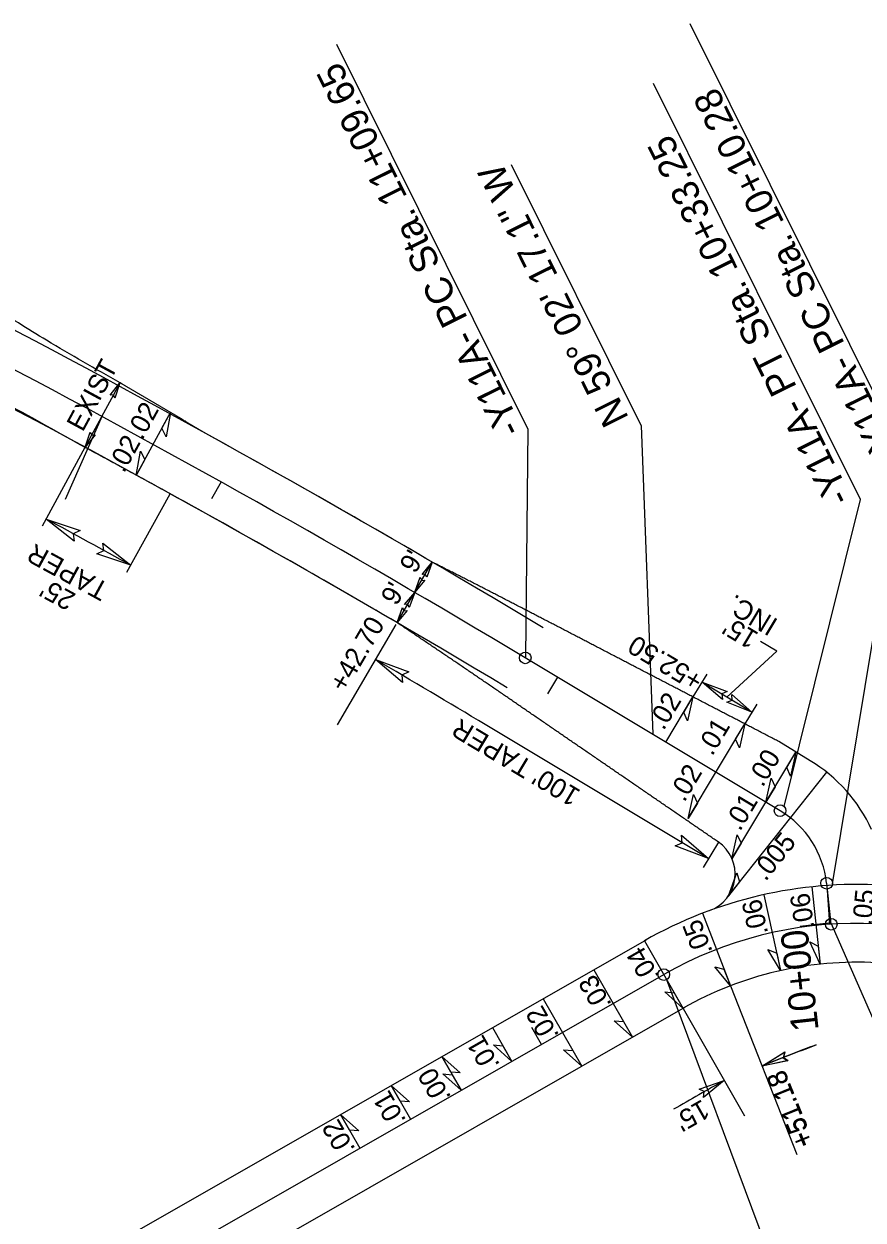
# Model space of a CAD drawing. Extents: x 472216 to 481979, y 489069 to 507339.
# Drawn here: x 475868.8 to 476084.6, y 502331.6 to 502639.2 of the extents above; entities that cross this region are included whole.
import ezdxf

# ---------------------------------------------------------------- set-up
doc = ezdxf.new("R2010")
doc.units = 0
for name, color, linetype in [('Old_Level_12', 7, 'Continuous'), ('Prop Drainage Structure Drop Inlet Grate 2 Narrow Slots and Sag Grates 840 24 CELL', 7, 'Continuous'), ('Prop Drainage Structure Drop Inlet Grate 2 Wide Slots and Sag Grates 840 22 Label', 7, 'Continuous'), ('Prop Drainage Structure Outlet Berm Ditch 850 10 CELL', 7, 'Continuous'), ('Prop Drainage Structure Pipe CSP 15in', 7, 'Continuous'), ('Prop Drainage Structure Pipe RCP 24in Class III Label', 7, 'Continuous'), ('Sheet Block Revision CELL', 7, 'Continuous'), ('Sheet Clip Boundary CELL', 7, 'Continuous'), ('Sheet North Arrow Point CELL', 7, 'Continuous'), ('Sheet PE Seal Cell', 7, 'Continuous'), ('Sheet Plan And Profile CELL', 7, 'Continuous'), ('Sheet Plot Border Outside CELL', 7, 'Continuous'), ('Sheet Profile Grid Major CELL', 7, 'Continuous'), ('Sheet Profile Grid Minor CELL', 7, 'Continuous')]:
    doc.layers.add(name, color=color, linetype=linetype)

msp = doc.modelspace()

# ---------------------------------------------------------------- linework, layer by layer
at = {"layer": 'Old_Level_12'}
for p, q in [((476095.02, 502528.88), (476040.15, 502639.21)), ((475998.49, 502534.91), (475949.28, 502633.88)), ((476083.89, 502516.94), (476030.7, 502623.9)), ((476027.52, 502535.97), (475994.2, 502602.98)), ((475888.94, 502538.42), (475879.42, 502516.88)), ((475997.83, 502476.34), (475998.49, 502534.91)), ((476027.52, 502535.97), (476030.49, 502456.52)), ((476076.71, 502418.03), (476095.02, 502528.88)), ((476064.3, 502437.93), (476083.89, 502516.94)), ((476123.29, 502300.73), (476076.37, 502407.98)), ((476034.08, 502393.42), (476074.2, 502285.86))]:
    msp.add_line(p, q, dxfattribs=at)
for centre in [(475997.73, 502476.18), (476063.24, 502436.87), (476075.23, 502418.22), (476076.4, 502407.68), (476076.4, 502407.68), (476033.34, 502394.73), (476033.34, 502394.73), (476033.34, 502394.73)]:
    msp.add_circle(centre, 1.5, dxfattribs=at)
at = {"layer": 'Prop Drainage Structure Drop Inlet Grate 2 Narrow Slots and Sag Grates 840 24 CELL'}
for points in [[(475906.5, 502539.27), (475905.38, 502533.05), (475904.28, 502535.21)], [(475897.67, 502523.09), (475898.78, 502529.31), (475899.88, 502527.15)], [(476040.85, 502466.13), (476039.48, 502459.95), (476038.47, 502462.16)], [(476054.19, 502459.19), (476052.81, 502453.02), (476051.81, 502455.23)], [(476067.33, 502451.95), (476065.96, 502445.78), (476064.95, 502447.98)], [(476059.6, 502439.06), (476060.97, 502445.23), (476061.98, 502443.02)], [(476039.59, 502434.87), (476040.96, 502441.04), (476041.97, 502438.83)], [(476050.88, 502424.53), (476052.25, 502430.7), (476053.26, 502428.49)], [(476049.96, 502414.95), (476052.12, 502420.9), (476052.83, 502418.58)], [(476073.53, 502397.4), (476070.91, 502403.16), (476073.05, 502402)], [(476063.38, 502395.74), (476060.13, 502401.17), (476062.38, 502400.26)], [(476050.47, 502391.84), (476046.45, 502396.71), (476048.81, 502396.15)], [(476038.29, 502386.04), (476033.58, 502390.26), (476036, 502390.06)], [(476025.27, 502378.6), (476020.56, 502382.82), (476022.98, 502382.62)], [(475994.26, 502372.4), (475989.55, 502376.62), (475991.97, 502376.42)], [(476012.25, 502371.16), (476007.53, 502375.38), (476009.95, 502375.17)], [(475976.28, 502373.64), (475980.99, 502369.43), (475978.57, 502369.63)], [(475981.24, 502364.96), (475976.52, 502369.18), (475978.94, 502368.98)], [(475963.25, 502366.2), (475967.96, 502361.99), (475965.55, 502362.19)], [(475950.23, 502358.76), (475954.94, 502354.54), (475952.52, 502354.75)]]:
    msp.add_lwpolyline(points, close=True, dxfattribs=at)
at = {"layer": 'Prop Drainage Structure Drop Inlet Grate 2 Wide Slots and Sag Grates 840 22 Label'}
for p, q in [((475897.67, 502523.09), (475906.5, 502539.27)), ((476062.4, 502477.9), (476058.21, 502480.41)), ((476049.56, 502466.07), (476062.4, 502477.9)), ((476044.38, 502472.01), (476040.85, 502466.13)), ((476056, 502462.21), (476043.13, 502469.93)), ((476033.87, 502454.49), (476040.85, 502466.13)), ((476057.25, 502464.29), (476054.19, 502459.19)), ((476039.59, 502434.87), (476054.19, 502459.19)), ((476050.88, 502424.53), (476067.33, 502451.95)), ((476049.82, 502414.73), (476075.23, 502446.78)), ((476059.04, 502415.27), (476063.38, 502395.74)), ((476071.44, 502417.29), (476073.53, 502397.4)), ((476043.26, 502410.49), (476050.47, 502391.84)), ((476028.37, 502403.41), (476038.29, 502386.04)), ((476015.35, 502395.97), (476025.27, 502378.6)), ((476050.47, 502391.84), (476067.53, 502348.46)), ((476002.33, 502388.52), (476012.25, 502371.16)), ((476038.29, 502386.04), (476054.11, 502358.36)), ((475989.3, 502381.08), (475994.26, 502372.4)), ((475976.28, 502373.64), (475981.24, 502364.96)), ((475963.25, 502366.2), (475968.21, 502357.52)), ((475950.23, 502358.76), (475955.19, 502350.08))]:
    msp.add_line(p, q, dxfattribs=at)
for points in [[(476048.41, 502465.48), (476043.17, 502469.89), (476049.64, 502467.5), (476048.29, 502466.9)], [(476050.86, 502466.74), (476056, 502462.21), (476049.59, 502464.75), (476050.95, 502465.32)], [(476065.23, 502372.58), (476058.53, 502371.15), (476064.39, 502374.79), (476064.03, 502373.35)], [(476065.34, 502372.66), (476058.65, 502371.2), (476064.48, 502374.86), (476064.14, 502373.43)], [(476042.42, 502365.24), (476048.89, 502367.49), (476043.54, 502363.15), (476043.71, 502364.62)]]:
    msp.add_lwpolyline(points, close=True, dxfattribs=at)
for centre, start, end in [((476392.64, 501524.75), 110.59975, 111.54419), ((476397.41, 501526.65), 110.91536, 111.85981), ((476492.74, 501573.08), 119.19234, 120.13679)]:
    msp.add_arc(centre, 910, start, end, dxfattribs=at)
at = {"layer": 'Prop Drainage Structure Outlet Berm Ditch 850 10 CELL'}
for points in [[(475890.96, 502543.7), (475893.5, 502546.93), (475892.2, 502543), (475891.81, 502543.8)], [(475887.1, 502533.57), (475884.56, 502530.34), (475885.86, 502534.26), (475886.25, 502533.47)], [(475881.74, 502506.22), (475874.57, 502511.87), (475883.29, 502508.96), (475881.51, 502508.1)], [(475889.11, 502505.67), (475896.27, 502500), (475887.56, 502502.93), (475889.33, 502503.78)], [(475971.18, 502497.64), (475973.82, 502500.79), (475972.39, 502496.91), (475972.03, 502497.72)], [(475971.94, 502496.18), (475969.3, 502493.03), (475970.73, 502496.91), (475971.09, 502496.1)], [(475966.64, 502489.87), (475969.29, 502493.02), (475967.86, 502489.14), (475967.49, 502489.95)], [(475967.39, 502488.39), (475964.75, 502485.24), (475966.18, 502489.12), (475966.54, 502488.31)], [(475966.18, 502469.86), (475959.2, 502475.75), (475967.82, 502472.56), (475966.02, 502471.76)], [(476037.93, 502430.54), (476044.85, 502424.59), (476036.26, 502427.87), (476038.07, 502428.65)]]:
    msp.add_lwpolyline(points, close=True, dxfattribs=at)
at = {"layer": 'Prop Drainage Structure Pipe RCP 24in Class III Label'}
for p, q in [((476070.96, 502449.73), (476062.9, 502454.66)), ((475884.66, 502321.3), (476028.98, 502403.75)), ((475894.58, 502303.94), (476038.9, 502386.39))]:
    msp.add_line(p, q, dxfattribs=at)
for centre, radius, start, end in [((474546.93, 500058), 2829, 59.70962, 61.077), ((474546.93, 500058), 2811, 59.70962, 61.077), ((476050.38, 502415.43), 40, 24.464, 59.0381), ((476041.69, 502420.58), 10, 290.1061, 55.6024), ((476082.94, 502307.9), 110, 86.4598, 119.7387), ((476082.94, 502307.9), 90, 86.612, 119.7387)]:
    msp.add_arc(centre, radius, start, end, dxfattribs=at)
for points in [[(475893.53, 502546.91), (475874.64, 502557.84), (475867.39, 502562.3), (475860.29, 502566.99), (475853.18, 502571.68), (475845.92, 502576.15), (475839.15, 502579.89), (475832.27, 502583.43), (475818.29, 502590.07), (475810.52, 502593.49), (475802.68, 502596.74), (475794.84, 502599.98), (475792.99, 502600.76)], [(475884.54, 502530.3), (475864.92, 502541.16), (475834.72, 502557.15), (475828.24, 502560.66), (475821.77, 502564.21), (475808.73, 502571.08), (475797.11, 502576.65)], [(475915.13, 502534.14), (475914.84, 502534.31), (475914.55, 502534.49), (475914.26, 502534.66), (475913.97, 502534.83), (475913.67, 502535.01), (475913.38, 502535.18), (475913.09, 502535.36), (475912.8, 502535.53), (475912.51, 502535.7), (475912.22, 502535.88), (475911.93, 502536.05), (475911.63, 502536.22), (475911.34, 502536.4), (475911.05, 502536.57), (475910.76, 502536.74), (475910.47, 502536.92), (475910.18, 502537.09), (475909.89, 502537.26), (475909.59, 502537.44), (475909.3, 502537.61), (475909.01, 502537.78), (475908.72, 502537.96), (475908.43, 502538.13), (475908.14, 502538.3), (475907.84, 502538.47), (475907.55, 502538.65), (475907.26, 502538.82), (475906.97, 502538.99), (475906.68, 502539.17), (475906.39, 502539.34), (475906.09, 502539.51), (475905.8, 502539.69), (475905.51, 502539.86), (475905.22, 502540.03), (475904.93, 502540.2), (475904.63, 502540.38), (475904.34, 502540.55), (475904.05, 502540.72), (475903.76, 502540.89), (475903.47, 502541.07), (475903.17, 502541.24), (475902.88, 502541.41), (475902.59, 502541.58), (475902.3, 502541.76), (475902.01, 502541.93), (475901.71, 502542.1), (475901.42, 502542.27), (475901.13, 502542.44), (475900.84, 502542.62), (475900.55, 502542.79), (475900.25, 502542.96), (475899.96, 502543.13), (475899.67, 502543.31), (475899.38, 502543.48), (475899.08, 502543.65), (475898.79, 502543.82), (475898.5, 502543.99), (475898.21, 502544.17), (475897.91, 502544.34), (475897.62, 502544.51), (475897.33, 502544.68), (475897.04, 502544.85), (475896.74, 502545.02), (475896.45, 502545.2), (475896.16, 502545.37), (475895.87, 502545.54), (475895.57, 502545.71), (475895.28, 502545.88), (475894.99, 502546.05), (475894.7, 502546.22), (475894.4, 502546.4), (475894.11, 502546.57), (475893.53, 502546.91)], [(475906.42, 502518.38), (475906.13, 502518.55), (475905.83, 502518.71), (475905.54, 502518.87), (475905.24, 502519.03), (475904.95, 502519.2), (475904.65, 502519.36), (475904.36, 502519.52), (475904.06, 502519.68), (475903.77, 502519.84), (475903.47, 502520.01), (475903.18, 502520.17), (475902.88, 502520.33), (475902.59, 502520.49), (475902.29, 502520.65), (475902, 502520.81), (475901.7, 502520.98), (475901.41, 502521.14), (475901.11, 502521.3), (475900.81, 502521.46), (475900.52, 502521.62), (475900.22, 502521.78), (475899.93, 502521.95), (475899.63, 502522.11), (475899.34, 502522.27), (475899.04, 502522.43), (475898.75, 502522.59), (475898.45, 502522.75), (475898.16, 502522.91), (475897.86, 502523.08), (475897.56, 502523.24), (475897.27, 502523.4), (475896.97, 502523.56), (475896.68, 502523.72), (475896.38, 502523.88), (475896.09, 502524.04), (475895.79, 502524.2), (475895.49, 502524.36), (475895.2, 502524.53), (475894.9, 502524.69), (475894.61, 502524.85), (475894.31, 502525.01), (475894.01, 502525.17), (475893.72, 502525.33), (475893.42, 502525.49), (475893.13, 502525.65), (475892.83, 502525.81), (475892.53, 502525.97), (475892.24, 502526.13), (475891.94, 502526.29), (475891.65, 502526.45), (475891.35, 502526.62), (475891.05, 502526.78), (475890.76, 502526.94), (475890.46, 502527.1), (475890.17, 502527.26), (475889.87, 502527.42), (475889.57, 502527.58), (475889.28, 502527.74), (475888.98, 502527.9), (475888.69, 502528.06), (475888.39, 502528.22), (475888.09, 502528.38), (475887.8, 502528.54), (475887.5, 502528.7), (475887.2, 502528.86), (475886.91, 502529.02), (475886.61, 502529.18), (475886.32, 502529.34), (475886.02, 502529.5), (475885.72, 502529.66), (475885.43, 502529.82), (475885.13, 502529.98), (475884.54, 502530.3)], [(476018.46, 502477.78), (476017.86, 502478.09), (476017.26, 502478.4), (476016.66, 502478.72), (476016.06, 502479.03), (476015.45, 502479.34), (476014.85, 502479.65), (476014.25, 502479.97), (476013.65, 502480.28), (476013.05, 502480.59), (476012.45, 502480.9), (476011.85, 502481.22), (476011.25, 502481.53), (476010.65, 502481.84), (476010.05, 502482.15), (476009.45, 502482.47), (476008.85, 502482.78), (476008.25, 502483.09), (476007.65, 502483.4), (476007.05, 502483.72), (476006.45, 502484.03), (476005.85, 502484.34), (476005.25, 502484.65), (476004.65, 502484.97), (476004.04, 502485.28), (476003.44, 502485.59), (476002.84, 502485.9), (476002.24, 502486.22), (476001.64, 502486.53), (476001.03, 502486.84), (476000.43, 502487.16), (475999.83, 502487.47), (475999.22, 502487.78), (475998.62, 502488.1), (475998.02, 502488.41), (475997.41, 502488.72), (475996.81, 502489.03), (475996.21, 502489.34), (475995.6, 502489.66), (475995, 502489.97), (475994.4, 502490.28), (475993.79, 502490.59), (475993.19, 502490.9), (475992.58, 502491.21), (475991.98, 502491.52), (475991.38, 502491.84), (475990.77, 502492.15), (475990.17, 502492.46), (475989.56, 502492.77), (475988.96, 502493.08), (475988.35, 502493.39), (475987.75, 502493.7), (475987.15, 502494.01), (475986.54, 502494.32), (475985.94, 502494.63), (475985.33, 502494.94), (475984.73, 502495.24), (475984.12, 502495.55), (475983.52, 502495.86), (475982.91, 502496.17), (475982.31, 502496.48), (475981.7, 502496.79), (475981.1, 502497.1), (475980.49, 502497.41), (475979.89, 502497.71), (475979.28, 502498.02), (475978.67, 502498.33), (475978.07, 502498.64), (475977.46, 502498.94), (475976.86, 502499.25), (475976.25, 502499.56), (475975.65, 502499.86), (475975.04, 502500.17), (475973.83, 502500.78)], [(476006.07, 502457.13), (476005.51, 502457.52), (476004.95, 502457.9), (476004.4, 502458.28), (476003.84, 502458.66), (476003.28, 502459.05), (476002.72, 502459.43), (476002.16, 502459.81), (476001.6, 502460.2), (476001.05, 502460.58), (476000.49, 502460.96), (475999.93, 502461.34), (475999.37, 502461.73), (475998.81, 502462.11), (475998.25, 502462.49), (475997.7, 502462.88), (475997.14, 502463.26), (475996.58, 502463.64), (475996.02, 502464.02), (475995.46, 502464.41), (475994.9, 502464.79), (475994.35, 502465.17), (475993.79, 502465.56), (475993.23, 502465.94), (475992.67, 502466.32), (475992.11, 502466.7), (475991.56, 502467.09), (475991, 502467.47), (475990.44, 502467.85), (475989.89, 502468.23), (475989.33, 502468.61), (475988.78, 502468.99), (475988.22, 502469.37), (475987.66, 502469.75), (475987.11, 502470.13), (475986.55, 502470.51), (475985.99, 502470.89), (475985.43, 502471.27), (475984.88, 502471.65), (475984.32, 502472.03), (475983.76, 502472.41), (475983.2, 502472.79), (475982.65, 502473.17), (475982.09, 502473.55), (475981.53, 502473.93), (475980.97, 502474.31), (475980.42, 502474.69), (475979.86, 502475.07), (475979.3, 502475.44), (475978.74, 502475.82), (475978.18, 502476.2), (475977.62, 502476.58), (475977.06, 502476.96), (475976.51, 502477.34), (475975.95, 502477.71), (475975.39, 502478.09), (475974.83, 502478.47), (475974.27, 502478.85), (475973.71, 502479.22), (475973.15, 502479.6), (475972.59, 502479.98), (475972.03, 502480.35), (475971.47, 502480.73), (475970.91, 502481.11), (475970.35, 502481.48), (475969.79, 502481.86), (475969.23, 502482.24), (475968.67, 502482.61), (475968.11, 502482.99), (475967.55, 502483.36), (475966.99, 502483.74), (475966.43, 502484.12), (475965.87, 502484.49), (475964.75, 502485.24)], [(476062.9, 502454.66), (476062.3, 502454.97), (476061.69, 502455.29), (476061.09, 502455.6), (476060.49, 502455.91), (476059.89, 502456.22), (476059.29, 502456.54), (476058.69, 502456.85), (476058.09, 502457.16), (476057.49, 502457.47), (476056.89, 502457.79), (476056.29, 502458.1), (476055.69, 502458.41), (476055.09, 502458.72), (476054.49, 502459.04), (476053.89, 502459.35), (476053.29, 502459.66), (476052.69, 502459.97), (476052.09, 502460.29), (476051.49, 502460.6), (476050.89, 502460.91), (476050.28, 502461.22), (476049.68, 502461.53), (476049.08, 502461.85), (476048.48, 502462.16), (476047.88, 502462.47), (476047.28, 502462.78), (476046.68, 502463.1), (476046.08, 502463.41), (476045.48, 502463.72), (476044.88, 502464.03), (476044.28, 502464.35), (476043.68, 502464.66), (476043.08, 502464.97), (476042.48, 502465.28), (476041.88, 502465.6), (476041.28, 502465.91), (476040.68, 502466.22), (476040.08, 502466.53), (476039.48, 502466.85), (476038.87, 502467.16), (476038.27, 502467.47), (476037.67, 502467.78), (476037.07, 502468.1), (476036.47, 502468.41), (476035.87, 502468.72), (476035.27, 502469.03), (476034.67, 502469.34), (476034.07, 502469.66), (476033.47, 502469.97), (476032.87, 502470.28), (476032.27, 502470.59), (476031.67, 502470.91), (476031.07, 502471.22), (476030.47, 502471.53), (476029.87, 502471.84), (476029.27, 502472.16), (476028.67, 502472.47), (476028.07, 502472.78), (476027.46, 502473.09), (476026.86, 502473.41), (476026.26, 502473.72), (476025.66, 502474.03), (476025.06, 502474.34), (476024.46, 502474.66), (476023.86, 502474.97), (476023.26, 502475.28), (476022.66, 502475.59), (476022.06, 502475.91), (476021.46, 502476.22), (476020.86, 502476.53), (476020.26, 502476.84), (476019.66, 502477.15), (476019.06, 502477.47), (476018.46, 502477.78)], [(476047.38, 502428.8), (476046.82, 502429.19), (476046.27, 502429.57), (476045.71, 502429.95), (476045.15, 502430.34), (476044.59, 502430.72), (476044.03, 502431.1), (476043.47, 502431.48), (476042.92, 502431.87), (476042.36, 502432.25), (476041.8, 502432.63), (476041.24, 502433.02), (476040.68, 502433.4), (476040.12, 502433.78), (476039.57, 502434.16), (476039.01, 502434.55), (476038.45, 502434.93), (476037.89, 502435.31), (476037.33, 502435.7), (476036.78, 502436.08), (476036.22, 502436.46), (476035.66, 502436.84), (476035.1, 502437.23), (476034.54, 502437.61), (476033.98, 502437.99), (476033.43, 502438.38), (476032.87, 502438.76), (476032.31, 502439.14), (476031.75, 502439.52), (476031.19, 502439.91), (476030.63, 502440.29), (476030.08, 502440.67), (476029.52, 502441.05), (476028.96, 502441.44), (476028.4, 502441.82), (476027.84, 502442.2), (476027.28, 502442.59), (476026.73, 502442.97), (476026.17, 502443.35), (476025.61, 502443.73), (476025.05, 502444.12), (476024.49, 502444.5), (476023.94, 502444.88), (476023.38, 502445.27), (476022.82, 502445.65), (476022.26, 502446.03), (476021.7, 502446.41), (476021.14, 502446.8), (476020.59, 502447.18), (476020.03, 502447.56), (476019.47, 502447.95), (476018.91, 502448.33), (476018.35, 502448.71), (476017.79, 502449.09), (476017.24, 502449.48), (476016.68, 502449.86), (476016.12, 502450.24), (476015.56, 502450.63), (476015, 502451.01), (476014.44, 502451.39), (476013.89, 502451.77), (476013.33, 502452.16), (476012.77, 502452.54), (476012.21, 502452.92), (476011.65, 502453.31), (476011.09, 502453.69), (476010.54, 502454.07), (476009.98, 502454.45), (476009.42, 502454.84), (476008.86, 502455.22), (476008.3, 502455.6), (476007.75, 502455.99), (476007.19, 502456.37), (476006.63, 502456.75), (476006.07, 502457.13)]]:
    msp.add_spline(points, degree=3, dxfattribs=at)
at = {"layer": 'Sheet Block Revision CELL'}
for p, q in [((475884.56, 502530.34), (475893.53, 502546.91)), ((475873.62, 502510.11), (475884.56, 502530.34)), ((475895.3, 502498.25), (475906.42, 502518.38)), ((475964.75, 502485.24), (475973.82, 502500.79)), ((475964.47, 502484.77), (475949.4, 502458.98)), ((476044.85, 502424.59), (475987.44, 502459.03)), ((476047.38, 502428.81), (476043.46, 502422.27))]:
    msp.add_line(p, q, dxfattribs=at)
for radius, start, end in [(2790, 61.077, 61.58494), (2800, 59.03808, 59.70971)]:
    msp.add_arc((474546.93, 500058), radius, start, end, dxfattribs=at)
at = {"layer": 'Sheet Clip Boundary CELL'}
msp.add_line((476075.29, 502417.63), (476075.99, 502407.65), dxfattribs=at)
at = {"layer": 'Sheet North Arrow Point CELL'}
for p, q in [((476063.24, 502436.87), (475997.73, 502476.18)), ((476076.4, 502407.68), (476075.23, 502418.22)), ((475741.43, 502227.96), (476033.34, 502394.73))]:
    msp.add_line(p, q, dxfattribs=at)
for centre, radius, start, end in [((474546.93, 500058), 2820, 59.03808, 65.52731), ((476050.38, 502415.43), 25, 6.389, 59.0381), ((476082.94, 502307.9), 100, 58.24, 119.7387)]:
    msp.add_arc(centre, radius, start, end, dxfattribs=at)
at = {"layer": 'Sheet PE Seal Cell'}
for p, q in [((475919.52, 502521.41), (475917.09, 502517.04)), ((476006, 502471.21), (476003.43, 502466.92)), ((476001.92, 502376.78), (475999.44, 502381.12)), ((476001.92, 502376.78), (475999.44, 502381.12))]:
    msp.add_line(p, q, dxfattribs=at)
at = {"layer": 'Sheet Plot Border Outside CELL'}
for radius in [2829, 2811]:
    msp.add_arc((474546.93, 500058), radius, 59.03808, 65.52731, dxfattribs=at)
at = {"layer": 'Sheet Profile Grid Minor CELL'}
msp.add_line((476076.37, 502408), (476068.42, 502407.11), dxfattribs=at)

# ---------------------------------------------------------------- texts
at = {"layer": 'Old_Level_12'}
for s, p in [('-Y11A- PC Sta. 11+09.65', (475997.17, 502535.05)), ('-Y11A- PC Sta. 10+10.28', (476094.09, 502528.49)), ('-Y11A- PT Sta. 10+33.25', (476081.79, 502517.34))]:
    msp.add_text(s, height=7, rotation=116.4407, dxfattribs=at).set_placement(p)
at = {"layer": 'Prop Drainage Structure Drop Inlet Grate 2 Narrow Slots and Sag Grates 840 24 CELL'}
for s, rotation, p in [('.02', 61.3858, (475899.24, 502531.98)), ('.02', 61.3858, (475894.52, 502523.5)), ('.02', 59.0381, (476033.28, 502457.31)), ('.01', 59.0381, (476045.8, 502450.73)), ('.00', 59.0381, (476058.78, 502442.7)), ('.02', 59.0381, (476038.63, 502438.86)), ('.01', 59.0381, (476052.93, 502431.4)), ('.005', 51.5491, (476059.52, 502418.53)), ('.06', 98.7682, (476072.09, 502406.79)), ('.05', 84.43, (476086.73, 502407.17)), ('.06', 102.5496, (476060.21, 502405.39)), ('.05', 111.144, (476045.98, 502400.69)), ('.04', 119.7383, (476032.42, 502394.3)), ('.03', 119.7387, (476020.09, 502387.06)), ('.02', 119.7387, (476006.56, 502379.1)), ('.01', 119.7387, (475991.32, 502371.5)), ('.00', 119.7387, (475978.79, 502363.2)), ('.01', 119.7387, (475967.22, 502357.25)), ('.02', 119.7387, (475954.16, 502349.87))]:
    msp.add_text(s, height=5, rotation=rotation, dxfattribs=at).set_placement(p)
at = {"layer": 'Prop Drainage Structure Drop Inlet Grate 2 Wide Slots and Sag Grates 840 22 Label'}
for s, rotation, p in [('INC.', 149.0033, (476063.03, 502485.85)), ("15'", 149.0033, (476058.01, 502482.45)), ('+52.50', 149.0381, (476043.87, 502471.59)), ('+51.18', 111.7898, (476071.84, 502351.36)), ('+51.18', 112.1054, (476072.07, 502351.48)), ("15'", 209.7039, (476043.22, 502362.77))]:
    msp.add_text(s, height=5, rotation=rotation, dxfattribs=at).set_placement(p)
at = {"layer": 'Prop Drainage Structure Pipe CSP 15in'}
for s, rotation, p in [('EXIST', 61.5861, (475883.94, 502534.07)), ('TAPER', 151.331, (475891.03, 502495.04)), ("9'", 59.7357, (475969.45, 502497.61)), ("25' ", 151.331, (475882.46, 502492.5)), ("9'", 59.7357, (475964.62, 502489.34)), ('+42.70', 59.7062, (475951.33, 502467.04)), ("100' TAPER", 149.0381, (476012.24, 502441.95))]:
    msp.add_text(s, height=5, rotation=rotation, dxfattribs=at).set_placement(p)
at = {"layer": 'Sheet Plan And Profile CELL'}
msp.add_text('N 59%%d 02\' 17.1" W', height=7, rotation=116.4407, dxfattribs=at).set_placement((476024.47, 502537.84))
at = {"layer": 'Sheet Profile Grid Major CELL'}
msp.add_text('10+00', height=7, rotation=96.389, dxfattribs=at).set_placement((476073.19, 502380.5))

doc.saveas('drawing.dxf')
